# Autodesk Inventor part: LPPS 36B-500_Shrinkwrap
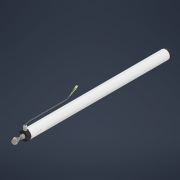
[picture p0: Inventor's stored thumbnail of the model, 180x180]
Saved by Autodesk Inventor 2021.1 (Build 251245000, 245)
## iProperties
Created: 2020-09
Part Number: LPPS 36B-500_Shrinkwrap
Material: Generic
Document SubType Name: Modeling
Designer: J. Nielson
Density: 1 g/cm^3
Appearance: Default
Author: J. Nielson
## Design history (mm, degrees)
derived "LPPS 36B-500.iam"
body "Solid1"
node "LPPS 36B Cable End Cap.iam:1::LPPS-36B PLASTIC CABLE END.ipt"
node "LPPS 36B Cable End Cap.iam:1::LPPS 36B- Cable Gland.ipt:1"
body "Solid2"
node "LPPS 36B Cable End Cap.iam:1::Cable Gland Cap.ipt:1"
body "Solid3"
node "LPPS 36B Cable End Cap.iam:1::Cable.ipt:1"
body "Solid4"
node "LPPS 36B Cable End Cap.iam:1::Cable Gland 2 of 2.ipt:1"
body "Solid5"
node "LPPS 36B Cable End Cap.iam:1::#6 Terminal Ring 22 - 18 AWG.i"
body "Solid6"
node "LPPS-36B-500 METAL HOUSING.ipt:1"
body "Solid7"
node "MALE Rod Eye SW.ipt:1"
body "Solid8"
node "LPPS-36B PLASTIC STROKE END.ipt:1"
body "Solid9"
node "LPPS-36B-500 Back Stop.ipt:1"
body "Solid10"
node "LPPS-36B-500 Front Stop.ipt:1"
body "Solid11"
node "AS 1427 - M3 x 16.ipt:1"
body "Solid12"
node "AS 1427 - M3 x 16.ipt:2"
body "Solid13"
node "AS 1427 - M3 x 16.ipt:3"
body "Solid14"
node "AS 1427 - M3 x 16.ipt:4"
body "Solid15"
node "AS 1112 - M8  Type 5.ipt:1"
body "Solid16"
node "AS 1237 - 8.ipt:1"
body "Solid17"
node "AS 1968 - 1976 - 8.ipt:1"
body "Solid18"
